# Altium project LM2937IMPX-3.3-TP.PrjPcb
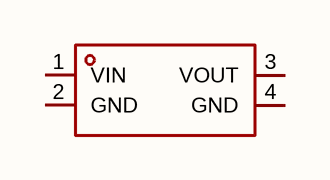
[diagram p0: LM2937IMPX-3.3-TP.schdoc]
1 sheet, 1 parts. Net scope: global (net labels, ports and power ports of the same name join across sheets).

## Sheet LM2937IMPX-3.3-TP.schdoc
size 127 x 101 mm

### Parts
U?  lm2937impx-3.3-tp  [SOT-223_L6.5-W3.5-P2.30-LS7.0-BR]  (value not drawn)

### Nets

Not connected (* = marked no-connect by the designer): U? 1(VIN) 2(GND) 3(VOUT) 4(GND)

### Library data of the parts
U? = lm2937impx-3.3-tp: 输出极性:正极;工作电压:28V;输出电压:3.3V;输出电流:300mA;电源纹波抑制比(PSRR):70dB@(1kHz);输出类型:固定;; Manufacturer: TECH PUBLIC(台舟); AddInBom: yes; ModelId: 925194bf9823436183a3e0b978a8d076; ModelName: SOT-223-4P_L6.5-W3.5-H1.6-LS7.0-P2.30; ModelTransform: 279.89794,255.905,0,180,0,0,0.0005,0.0005,0; Output Configuration: 正极; Voltage - Supply: 28V; Output Voltage: 3.3V; Output Current: 300mA; standby current: 1.5uA; Output Type: 固定; Number of Outputs: 1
